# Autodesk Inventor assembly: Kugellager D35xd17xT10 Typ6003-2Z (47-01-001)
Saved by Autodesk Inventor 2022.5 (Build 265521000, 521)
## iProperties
Created: 2024-12
Part Number: Kugellager D35xd17xT10 Typ6003-2Z (47-01-001)
Document SubType Name: Assembly
Designer: AdminForWorker
Title: Kugellager D35xd17xT10 Typ6003-2Z (47-01-001) v1
Author: AdminForWorker
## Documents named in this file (5)
- c:\worker\convert-fusion-r05-cosv3\tmp\job-1\494\temp\files\bac78c07-960d-4446-9a29-ed9f0069b553\570677f1-3019-4672-9e17-04e31c28d139.zip.iam
- c:\worker\convert-fusion-r05-cosv3\tmp\job-1\494\temp\files\bac78c07-960d-4446-9a29-ed9f0069b553\6003-2Z_InnerRing.ipt
- c:\worker\convert-fusion-r05-cosv3\tmp\job-1\494\temp\files\bac78c07-960d-4446-9a29-ed9f0069b553\6003-2Z_Ball.ipt
- c:\worker\convert-fusion-r05-cosv3\tmp\job-1\494\temp\files\bac78c07-960d-4446-9a29-ed9f0069b553\6003-2Z_OuterRing.ipt
- c:\worker\convert-fusion-r05-cosv3\tmp\job-1\494\temp\files\bac78c07-960d-4446-9a29-ed9f0069b553\6003-2Z_Shield.ipt
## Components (15 placed, 4 different names)
1. 6003-2Z_InnerRing:1
2. 6003-2Z_Ball:1
3. 6003-2Z_Ball:2
4. 6003-2Z_Ball:3
5. 6003-2Z_Ball:4
6. 6003-2Z_Ball:5
7. 6003-2Z_Ball:6
8. 6003-2Z_Ball:7
9. 6003-2Z_Ball:8
10. 6003-2Z_Ball:9
11. 6003-2Z_Ball:10
12. 6003-2Z_Ball:11
13. 6003-2Z_OuterRing:1
14. 6003-2Z_Shield:1
15. 6003-2Z_Shield:2
